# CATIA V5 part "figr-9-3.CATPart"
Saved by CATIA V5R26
Part number: Part1
Bounding box of the stored display mesh (mm): x -25 to 69.61, y -164.735 to 0, z 0 to 45
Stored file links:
  D:\_Deepak\CATIA\CATIA V5-6R2016_Deepak\Resources\Part files\Partfiles\c09_catia_v5_6r2016_prt\figr-9-3.CATPart
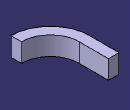
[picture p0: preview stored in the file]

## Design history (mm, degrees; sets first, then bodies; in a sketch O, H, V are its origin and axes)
Body1 (main body)
  Sketch1 on xy-plane, origin (0, 0, 0), H (1, 0, 0), V (0, 1, 0)
    line L1 (0, 0) -> (0, -70.1255)
    arc A1 centre (69.6095, -70.1255) radius 69.6095 from (0, -70.1255) to (69.6095, -139.7351) ccw
    vertical: L1 V
    tangency: A1 L1
  Sketch2 on zx-plane, origin (0, 0, 0), H (-1, 0, 0), V (0, 0, 1)
    point P1 (0, 0)
    line L1 (0, 0) -> (25, 0)
    line L2 (25, 0) -> (25, 45)
    line L3 (25, 45) -> (0, 45)
    line L4 (0, 45) -> (0, 0)
    length L3 = 25
    length L2 = 45
    coincidence: P1 H, P1 O
    horizontal: L1 H, L3 H
    vertical: L2 V, L4 V
  Rib1: profile Sketch2, centre curve Sketch1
